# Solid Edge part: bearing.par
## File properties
Title: Ball Bearing
Subject: Wheel Assembly
Author: kiyo
Keywords: Ball Bearing
Comments: Ball Bearing 20mm Shaft Diameter
Template: metric.par
Last saved by: edge
Revision: 30
Application: Solid Edge
File Size: 0
Number of Sheets: 0
Number of Objects: 0
Username: kiyo
文書内容のタイプ: 0
Material: Bronze, 90%
Face Style: Bronze
Fill Style: ANSI33(Brass)
Virtual Style: Brushed bronze
Coef. of Thermal Exp: 1.8e-05
Thermal Conductivity: 189.0
Specific Heat: 377.0
Modulus of Elasticity: 117210869000.0
Poisson's Ratio: 0.36
Yield Stress: 372316878.0
Ultimate Stress: 420580177.0
Elongation: 0.0
Category: Bearing
Manager: Brian Little
Company: Wheels R Us
Density: 5000
Accuracy: 0.99
Document Number: BB-820
Revision: 1
Project Name: Trolley Wheel Assembly
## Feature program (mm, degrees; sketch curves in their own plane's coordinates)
sketch for "unnamed RevolvedProtrusion 1" plane through (0, 0, 0) normal (0, -1, 0) x-axis (1, 0, 0)
  line (-41.3956, 17.2482) -> (-41.3956, 32.2482)
  line (-41.3956, 32.2482) -> (-26.3956, 32.2482)
  line (-26.3956, 32.2482) -> (-26.3956, 17.2482)
  line (-26.3956, 17.2482) -> (-41.3956, 17.2482)
revolve "unnamed RevolvedProtrusion 1" add finite 360 deg about sketch line (-41.3956, 7.2482) -> (-16.9346, 7.2482)
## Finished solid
Body 1: solid body, 4 faces, 4 edges, 0 vertices.
  Faces by surface: cylinder 2, plane 2
  Edges by curve: circle 4
Bounding box of the edges (mm): 15.000 x 50.000 x 50.000, from (-41.3956, -25, -17.7518) to (-26.3956, 25, 32.2482).
Cylindrical faces by radius (mm): R10 x1, R25 x1
Planar faces by outward normal: +x 1, -x 1
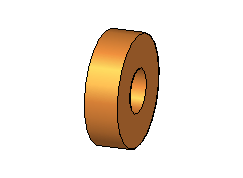
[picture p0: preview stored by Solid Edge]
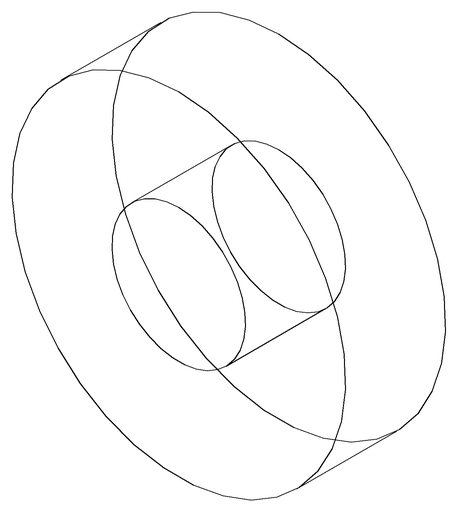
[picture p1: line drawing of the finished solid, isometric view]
